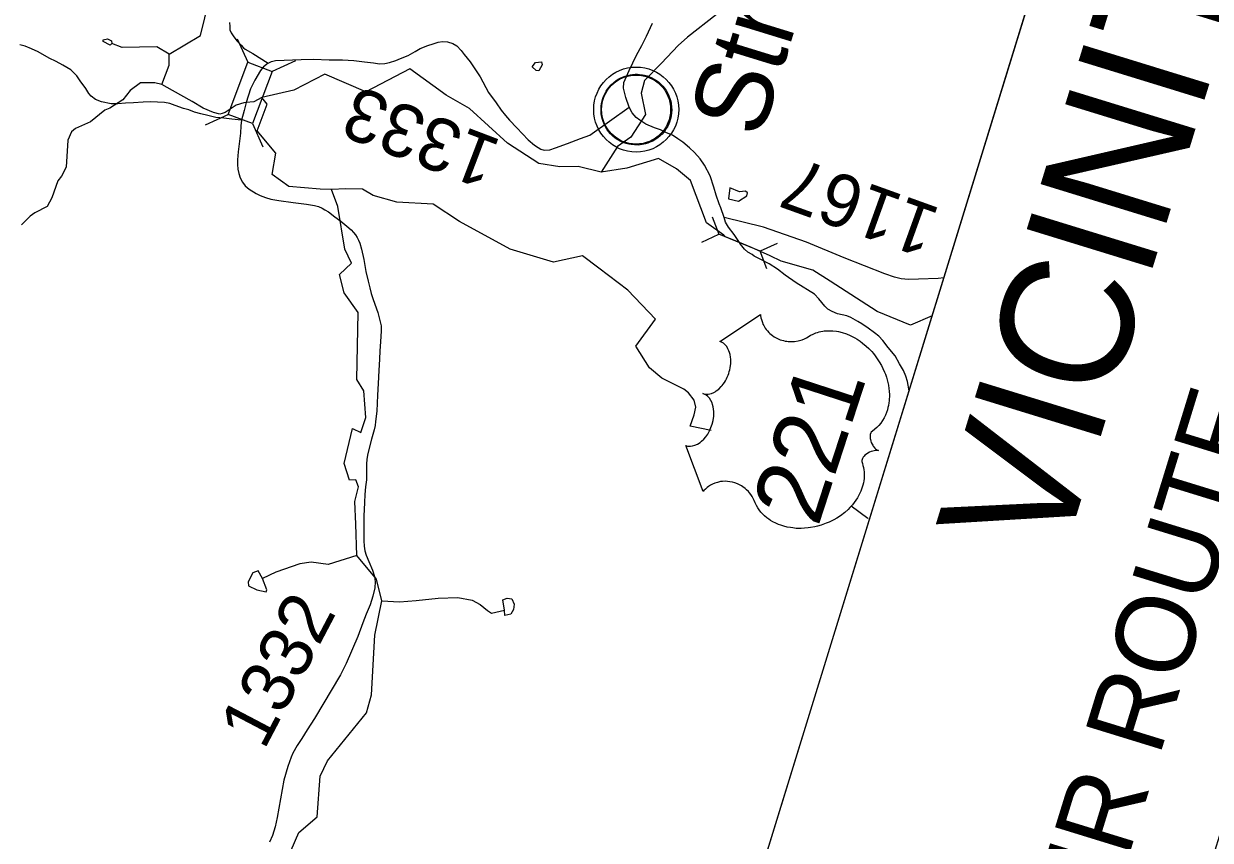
# Model space of a CAD drawing. Extents: x 1347947 to 1350662, y 1027710 to 1030532.
# Drawn here: x 1348252.2 to 1348353.5, y 1028802.3 to 1028872.1 of the extents above; entities that cross this region are included whole.
import ezdxf

# ---------------------------------------------------------------- set-up
doc = ezdxf.new("R2010")
doc.units = 0
for name, color, linetype in [('Default', 7, 'Continuous'), ('Prop Leader Line Light', 7, 'Continuous'), ('Prop WCC CELL', 7, 'Continuous')]:
    doc.layers.add(name, color=color, linetype=linetype)

msp = doc.modelspace()

# ---------------------------------------------------------------- linework, layer by layer
at = {"layer": 'Default'}
for p, q in [((1348270.41, 1028870.75), (1348271.31, 1028868.76)), ((1348275.38, 1028868.88), (1348273.4, 1028867.98)), ((1348269.67, 1028864.29), (1348267.68, 1028863.39)), ((1348271.71, 1028863.52), (1348272.6, 1028861.54)), ((1348310.96, 1028855.55), (1348311.54, 1028854.06)), ((1348310.08, 1028853.4), (1348311.54, 1028854.06)), ((1348315.07, 1028852.61), (1348311.54, 1028854.06)), ((1348316.53, 1028853.27), (1348315.07, 1028852.61)), ((1348315.65, 1028851.12), (1348315.07, 1028852.61))]:
    msp.add_line(p, q, dxfattribs=at)
for points in [[(1348333.37, 1028883.64), (1348331.83, 1028883.24), (1348328.68, 1028882.36), (1348316.42, 1028876.72), (1348311.33, 1028872.83), (1348308.86, 1028870.92), (1348308.06, 1028870.18), (1348306.64, 1028868.69), (1348305.18, 1028867.21), (1348304.9, 1028866.11), (1348305.29, 1028864.31)], [(1348271.18, 1028865.33), (1348270.97, 1028865.29), (1348270.31, 1028865.1), (1348269.9, 1028864.8), (1348269.38, 1028864.48), (1348269.13, 1028864.38), (1348268.93, 1028864.32), (1348268.37, 1028864.48), (1348267.5, 1028864.83), (1348266.57, 1028865.4), (1348264.87, 1028866.34), (1348263.98, 1028866.86), (1348264.61, 1028868.51), (1348264.61, 1028869.45), (1348267.27, 1028871.06), (1348268.01, 1028874.08), (1348268.57, 1028875.2), (1348268.36, 1028876.03), (1348268.81, 1028878.77), (1348269.15, 1028880.07)], [(1348269.75, 1028872.17), (1348269.78, 1028871.81), (1348269.79, 1028871.54), (1348269.89, 1028871.29), (1348270.05, 1028871.01), (1348270.38, 1028870.59), (1348270.74, 1028870.23), (1348270.94, 1028869.99), (1348271.1, 1028869.87), (1348271.74, 1028869.52), (1348273.05, 1028868.69)], [(1348303.87, 1028864.92), (1348303.6, 1028865.75), (1348303.4, 1028866.56), (1348303.44, 1028867.02), (1348303.87, 1028868.06), (1348304.52, 1028869.36), (1348304.97, 1028870.2), (1348305.36, 1028870.99), (1348305.86, 1028872.09)], [(1348259.71, 1028870.37), (1348259.55, 1028870.22), (1348258.95, 1028870.54), (1348258.96, 1028870.69), (1348259.33, 1028870.77), (1348259.68, 1028870.58), (1348259.71, 1028870.37)], [(1348259.71, 1028870.37), (1348259.55, 1028870.22), (1348258.95, 1028870.54), (1348258.96, 1028870.69), (1348259.33, 1028870.77), (1348259.68, 1028870.58), (1348259.71, 1028870.37)], [(1348270.78, 1028863.82), (1348269.96, 1028863.91), (1348269.26, 1028863.97), (1348268.57, 1028864.04), (1348267.89, 1028864.2), (1348267.31, 1028864.34), (1348266.75, 1028864.51), (1348266.29, 1028864.71), (1348265.81, 1028864.81), (1348265.12, 1028865.07), (1348264.66, 1028865.23), (1348264.19, 1028865.32), (1348263.59, 1028865.35), (1348262.99, 1028865.37), (1348262.37, 1028865.36), (1348261.56, 1028865.3), (1348260.88, 1028865.27), (1348260.21, 1028865.2), (1348259.64, 1028865.21), (1348258.82, 1028865.39), (1348258.3, 1028865.57), (1348257.94, 1028865.85), (1348257.75, 1028866.1), (1348257.48, 1028866.51), (1348257.01, 1028867.16), (1348256.7, 1028867.59), (1348256.2, 1028868.11), (1348255.51, 1028868.52), (1348254.95, 1028868.84), (1348254.34, 1028869.12), (1348253.4, 1028869.64), (1348252.85, 1028869.92), (1348252.3, 1028870.13), (1348251.85, 1028870.25)], [(1348264.61, 1028869.45), (1348263.54, 1028870.07), (1348260.57, 1028870.03), (1348259.71, 1028870.37)], [(1348273.05, 1028868.69), (1348273.34, 1028868.82), (1348273.69, 1028868.9), (1348275.86, 1028868.99), (1348276.91, 1028869.03), (1348278.26, 1028868.96), (1348279.41, 1028868.98), (1348280.36, 1028868.91), (1348281.29, 1028868.8), (1348282.04, 1028868.71), (1348282.56, 1028868.63), (1348283.02, 1028868.66), (1348283.42, 1028868.75), (1348283.96, 1028868.92), (1348284.34, 1028869.07), (1348285.01, 1028869.35), (1348285.61, 1028869.67), (1348286.02, 1028869.93), (1348286.68, 1028870.18), (1348287.13, 1028870.34), (1348287.58, 1028870.49), (1348287.94, 1028870.53), (1348288.38, 1028870.5), (1348288.81, 1028870.37), (1348289.16, 1028870.17), (1348289.54, 1028869.77), (1348289.8, 1028869.42), (1348290.29, 1028868.79), (1348291.15, 1028867.52), (1348291.88, 1028866.19), (1348292.51, 1028865.3), (1348292.94, 1028864.68), (1348293.33, 1028864.22), (1348293.66, 1028863.81), (1348294.3, 1028863.15), (1348294.76, 1028862.64), (1348295.26, 1028862.14), (1348295.81, 1028861.67), (1348296.1, 1028861.47), (1348296.34, 1028861.33), (1348296.62, 1028861.26), (1348297.1, 1028861.27), (1348297.59, 1028861.44), (1348298.61, 1028861.83), (1348299.72, 1028862.26), (1348300.52, 1028862.52), (1348303.87, 1028864.92)], [(1348295.93, 1028868.05), (1348295.59, 1028868.37), (1348295.87, 1028868.75), (1348296.4, 1028868.81), (1348296.46, 1028868.54), (1348296.18, 1028868.02), (1348295.93, 1028868.05)], [(1348295.93, 1028868.05), (1348295.59, 1028868.37), (1348295.87, 1028868.75), (1348296.4, 1028868.81), (1348296.46, 1028868.54), (1348296.18, 1028868.02), (1348295.93, 1028868.05)], [(1348273.05, 1028868.69), (1348272.65, 1028868.37), (1348272.39, 1028868.07), (1348271.9, 1028867.22), (1348271.55, 1028866.49), (1348271.18, 1028865.33)], [(1348301.5, 1028859.36), (1348299.53, 1028859.84), (1348297.97, 1028859.82), (1348296.16, 1028860.12), (1348293.49, 1028861.85), (1348290.26, 1028864.81), (1348288.25, 1028865.96), (1348285.14, 1028868.19), (1348281.4, 1028866.23), (1348277.88, 1028867.75), (1348275.23, 1028866.37), (1348272.5, 1028865.75)], [(1348263.98, 1028866.86), (1348263.38, 1028867.01), (1348262.15, 1028866.99), (1348261.26, 1028866.36), (1348260.63, 1028865.56), (1348259.52, 1028864.83), (1348259.1, 1028864.67), (1348257.89, 1028863.67), (1348256.61, 1028863.09), (1348256.26, 1028862.81), (1348255.95, 1028862.1), (1348255.8, 1028859.81), (1348255.39, 1028859.04), (1348255.09, 1028858.63), (1348254.58, 1028857.18), (1348254.19, 1028856.43), (1348253.13, 1028855.89), (1348252.73, 1028855.62), (1348251.99, 1028854.86)], [(1348272.5, 1028865.75), (1348271.84, 1028865.39), (1348271.18, 1028865.33)], [(1348278.45, 1028857.9), (1348277.5, 1028857.93), (1348274.83, 1028858.14), (1348273.38, 1028859.18), (1348273.72, 1028860.99), (1348272.1, 1028862.9), (1348272.97, 1028865.19), (1348272.5, 1028865.75)], [(1348271.18, 1028865.33), (1348270.99, 1028864.64), (1348270.78, 1028863.82)], [(1348312, 1028855.49), (1348311.7, 1028856.31), (1348311.56, 1028856.66), (1348311.31, 1028857.41), (1348311.1, 1028858.09), (1348310.8, 1028859.05), (1348310.31, 1028859.98), (1348309.94, 1028860.51), (1348309.47, 1028861.05), (1348309.02, 1028861.46), (1348308.47, 1028861.92), (1348308.04, 1028862.22), (1348307.57, 1028862.52), (1348307.08, 1028862.73), (1348306.55, 1028862.98), (1348306.04, 1028863.16), (1348305.31, 1028863.47), (1348304.8, 1028863.8), (1348304.49, 1028864.03), (1348304.15, 1028864.43), (1348303.87, 1028864.92)], [(1348270.78, 1028863.82), (1348270.73, 1028863.33), (1348270.68, 1028862.71), (1348270.48, 1028861.1), (1348270.43, 1028860.41), (1348270.43, 1028860.03), (1348270.46, 1028859.63), (1348270.55, 1028859.26), (1348270.67, 1028858.88), (1348270.86, 1028858.51), (1348271.09, 1028858.19), (1348271.42, 1028857.92), (1348272.03, 1028857.55), (1348272.38, 1028857.38), (1348272.83, 1028857.2), (1348273.28, 1028857.06), (1348273.95, 1028856.94), (1348275.2, 1028856.77), (1348276.33, 1028856.63), (1348277, 1028856.51), (1348277.36, 1028856.43), (1348277.66, 1028856.3), (1348277.9, 1028856.16), (1348278.2, 1028855.98), (1348278.75, 1028855.56), (1348279.27, 1028855.17), (1348279.78, 1028854.76), (1348280.15, 1028854.43), (1348280.34, 1028854.22), (1348280.51, 1028854.02), (1348280.66, 1028853.79), (1348280.76, 1028853.56), (1348280.87, 1028853.29), (1348281.01, 1028852.79), (1348281.22, 1028851.9), (1348281.4, 1028850.89), (1348281.59, 1028850.04), (1348281.73, 1028849.47), (1348281.86, 1028848.99), (1348282.02, 1028848.49), (1348282.41, 1028847.37), (1348282.59, 1028846.69), (1348282.69, 1028846.23), (1348282.69, 1028845.81), (1348282.64, 1028844.87), (1348282.6, 1028844.11), (1348282.55, 1028843.39), (1348282.51, 1028842.41), (1348282.45, 1028841.31), (1348282.4, 1028840.3), (1348282.33, 1028838.95), (1348282.22, 1028838.07), (1348282.18, 1028837.71), (1348282.1, 1028837.36), (1348281.87, 1028836.54), (1348281.64, 1028835.68), (1348281.53, 1028835.18), (1348281.49, 1028834.82), (1348281.46, 1028834.45), (1348281.45, 1028833.56), (1348281.45, 1028833.08), (1348281.37, 1028832.47), (1348281.31, 1028831.82), (1348281.27, 1028831.13), (1348281.23, 1028829.98), (1348281.21, 1028828.59), (1348281.21, 1028827.85), (1348281.24, 1028827.4), (1348281.32, 1028827), (1348281.43, 1028826.64), (1348281.64, 1028826.09), (1348281.97, 1028825.36), (1348282.14, 1028824.81), (1348282.19, 1028824.35), (1348282.16, 1028823.84), (1348282, 1028823.12), (1348281.75, 1028822.39), (1348281.41, 1028821.6), (1348281.14, 1028820.86), (1348280.72, 1028819.69), (1348279.71, 1028817.37), (1348279.24, 1028816.4), (1348277, 1028812.67), (1348276.39, 1028811.71), (1348275.93, 1028810.98), (1348275.54, 1028810.38), (1348275.17, 1028809.72), (1348275.01, 1028809.37), (1348274.72, 1028808.58), (1348274.4, 1028807.42), (1348274.11, 1028805.82), (1348273.81, 1028804.21), (1348273.64, 1028803.42), (1348273.43, 1028802.68), (1348273.17, 1028802.12)], [(1348305.29, 1028864.31), (1348304.01, 1028862.37)], [(1348304.01, 1028862.37), (1348302.89, 1028861.55)], [(1348302.89, 1028861.55), (1348301.5, 1028859.36)], [(1348313.29, 1028853.37), (1348312.11, 1028853.85), (1348311.96, 1028853.99), (1348310.5, 1028855.04), (1348309.11, 1028858.67), (1348307.92, 1028859.64), (1348306.39, 1028860.53), (1348303.69, 1028859.71), (1348301.5, 1028859.36)], [(1348274.35, 1028799.93), (1348275.67, 1028802.95), (1348277.23, 1028804.28), (1348277.5, 1028807.75), (1348278.13, 1028809.06), (1348281.46, 1028813.16), (1348281.89, 1028814.7), (1348282.16, 1028819.8), (1348282.75, 1028822.73), (1348282.29, 1028824.59), (1348280.62, 1028826.62), (1348280.55, 1028829.28), (1348280.46, 1028831.23), (1348280.76, 1028832.49), (1348280.55, 1028833.07), (1348279.99, 1028833.05), (1348279.55, 1028834.48), (1348280.25, 1028837.47), (1348280.96, 1028837.12), (1348281.38, 1028838.4), (1348281.21, 1028840.67), (1348280.62, 1028841.65), (1348280.74, 1028847.37), (1348279.54, 1028849.07), (1348279.13, 1028850.61), (1348280.18, 1028851.58), (1348279.61, 1028852.78), (1348278.99, 1028856.44), (1348278.45, 1028857.9)], [(1348310.89, 1028837.28), (1348309.08, 1028837.66), (1348309.44, 1028838.64), (1348309.57, 1028839.29), (1348309.43, 1028839.87), (1348308.95, 1028840.51), (1348308.54, 1028840.82), (1348306.66, 1028841.75), (1348305.61, 1028842.66), (1348304.45, 1028844.5), (1348306.14, 1028846.81), (1348303.78, 1028849.28), (1348301.3, 1028851.17), (1348299.9, 1028852.22), (1348297.41, 1028851.69), (1348293.71, 1028852.8), (1348289.4, 1028855.15), (1348287.14, 1028856.62), (1348284.05, 1028856.81), (1348282.03, 1028857.38), (1348281.11, 1028857.93), (1348279.69, 1028857.94), (1348278.45, 1028857.9)], [(1348312.36, 1028857.1), (1348313.23, 1028856.9), (1348313.94, 1028857.36), (1348313.98, 1028857.59), (1348313.83, 1028857.74), (1348313.3, 1028857.69), (1348312.49, 1028858.03), (1348312.36, 1028857.1)], [(1348330.75, 1028850.33), (1348330.26, 1028850.29), (1348328.58, 1028850.23), (1348327.77, 1028850.21), (1348327.41, 1028850.23), (1348327.11, 1028850.26), (1348326.53, 1028850.4), (1348325.71, 1028850.67), (1348322.23, 1028852.04), (1348319.04, 1028853.4), (1348315.36, 1028854.67), (1348312, 1028855.49)], [(1348327.78, 1028840.69), (1348327.64, 1028841.48), (1348327.51, 1028841.94), (1348327.31, 1028842.41), (1348326.97, 1028843), (1348326.59, 1028843.66), (1348326, 1028844.38), (1348325.54, 1028844.99), (1348325.21, 1028845.34), (1348324.82, 1028845.64), (1348324.29, 1028846.05), (1348323.75, 1028846.42), (1348323.4, 1028846.62), (1348322.82, 1028846.95), (1348322.46, 1028847.1), (1348321.68, 1028847.27), (1348321.22, 1028847.46), (1348320.85, 1028847.66), (1348320.59, 1028847.91), (1348320.08, 1028848.54), (1348319.72, 1028848.93), (1348318.13, 1028849.91), (1348317.2, 1028850.57), (1348316.56, 1028851.09), (1348315.84, 1028851.53), (1348315.07, 1028851.92), (1348314.55, 1028852.2), (1348314.39, 1028852.32), (1348314.01, 1028852.53), (1348313.72, 1028852.8), (1348313.38, 1028853.22), (1348313.29, 1028853.37), (1348312.86, 1028854.03), (1348312.37, 1028854.66), (1348312.11, 1028855.11), (1348312, 1028855.49)], [(1348316.85, 1028851.75), (1348315.91, 1028852.22), (1348314.34, 1028852.94), (1348313.29, 1028853.37)], [(1348319.58, 1028850.99), (1348316.85, 1028851.75)], [(1348329.76, 1028847.09), (1348327.9, 1028846.28), (1348325.06, 1028847.45), (1348321.05, 1028850.06), (1348319.58, 1028850.99)], [(1348324.27, 1028829.76), (1348322.84, 1028830.82)], [(1348324.41, 1028829.72), (1348324.36, 1028829.73)], [(1348280.62, 1028826.62), (1348278.19, 1028825.83), (1348276.73, 1028826.03), (1348275.77, 1028825.9), (1348273.72, 1028825.19), (1348272.57, 1028824.63)], [(1348272.57, 1028824.63), (1348272.2, 1028825.31), (1348271.73, 1028825.13), (1348271.35, 1028824.35), (1348271.38, 1028824.03), (1348272.08, 1028823.68), (1348272.89, 1028823.5), (1348272.95, 1028823.68), (1348272.57, 1028824.63)], [(1348272.57, 1028824.63), (1348272.2, 1028825.31), (1348271.73, 1028825.13), (1348271.35, 1028824.35), (1348271.38, 1028824.03), (1348272.08, 1028823.68), (1348272.89, 1028823.5), (1348272.95, 1028823.68), (1348272.57, 1028824.63)], [(1348282.75, 1028822.73), (1348284.27, 1028822.64), (1348285.7, 1028822.75), (1348287.56, 1028822.95), (1348289.26, 1028823.03), (1348290.46, 1028822.78), (1348291.15, 1028822.43), (1348291.78, 1028821.9), (1348292.12, 1028821.69), (1348293.23, 1028821.95)], [(1348293.23, 1028821.95), (1348293.1, 1028822.81), (1348293.46, 1028822.95), (1348293.85, 1028822.91), (1348294.05, 1028822.44), (1348293.99, 1028821.99), (1348293.78, 1028821.61), (1348293.27, 1028821.49), (1348293.23, 1028821.95)], [(1348293.23, 1028821.95), (1348293.1, 1028822.81), (1348293.46, 1028822.95), (1348293.85, 1028822.91), (1348294.05, 1028822.44), (1348293.99, 1028821.99), (1348293.78, 1028821.61), (1348293.27, 1028821.49), (1348293.23, 1028821.95)]]:
    msp.add_lwpolyline(points, dxfattribs=at)
for points in [[(1348273.4, 1028867.98), (1348271.72, 1028863.52), (1348269.63, 1028864.3), (1348271.31, 1028868.76)], [(1348303.1, 1028862.03), (1348302.91, 1028862.14), (1348302.69, 1028862.28), (1348302.46, 1028862.47), (1348302.29, 1028862.65), (1348302.12, 1028862.84), (1348301.97, 1028863.04), (1348301.86, 1028863.23), (1348301.75, 1028863.46), (1348301.65, 1028863.71), (1348301.58, 1028863.96), (1348301.53, 1028864.17), (1348301.5, 1028864.38), (1348301.48, 1028864.61), (1348301.48, 1028864.84), (1348301.49, 1028865.01), (1348301.52, 1028865.2), (1348301.54, 1028865.35), (1348301.61, 1028865.59), (1348301.67, 1028865.75), (1348301.74, 1028865.96), (1348301.83, 1028866.13), (1348301.92, 1028866.29), (1348302.04, 1028866.46), (1348302.17, 1028866.63), (1348302.35, 1028866.84), (1348302.56, 1028867.02), (1348302.75, 1028867.17), (1348302.95, 1028867.31), (1348303.11, 1028867.39), (1348303.32, 1028867.49), (1348303.54, 1028867.57), (1348303.74, 1028867.63), (1348303.96, 1028867.69), (1348304.18, 1028867.72), (1348304.39, 1028867.73), (1348304.59, 1028867.73), (1348304.77, 1028867.72), (1348305.01, 1028867.69), (1348305.19, 1028867.65), (1348305.41, 1028867.59), (1348305.62, 1028867.52), (1348305.82, 1028867.43), (1348306.01, 1028867.33), (1348306.21, 1028867.2), (1348306.41, 1028867.06), (1348306.56, 1028866.91), (1348306.75, 1028866.73), (1348306.9, 1028866.54), (1348307.03, 1028866.36), (1348307.16, 1028866.15), (1348307.27, 1028865.9), (1348307.36, 1028865.66), (1348307.43, 1028865.44), (1348307.47, 1028865.25), (1348307.51, 1028864.96), (1348307.52, 1028864.67), (1348307.51, 1028864.43), (1348307.47, 1028864.18), (1348307.44, 1028864.01), (1348307.39, 1028863.84), (1348307.33, 1028863.64), (1348307.26, 1028863.49), (1348307.17, 1028863.29), (1348307.05, 1028863.09), (1348306.95, 1028862.94), (1348306.82, 1028862.77), (1348306.69, 1028862.62), (1348306.56, 1028862.51), (1348306.33, 1028862.31), (1348306.11, 1028862.15), (1348305.89, 1028862.03), (1348305.66, 1028861.92), (1348305.47, 1028861.85), (1348305.28, 1028861.79), (1348304.98, 1028861.73), (1348304.83, 1028861.71), (1348304.66, 1028861.69), (1348304.33, 1028861.7), (1348304.05, 1028861.72), (1348303.85, 1028861.76), (1348303.62, 1028861.82), (1348303.45, 1028861.88), (1348303.22, 1028861.97)], [(1348308.73, 1028836), (1348308.86, 1028835.96), (1348309.03, 1028835.95), (1348309.11, 1028835.94), (1348309.29, 1028835.97), (1348309.5, 1028836.03), (1348309.73, 1028836.13), (1348309.94, 1028836.27), (1348310.07, 1028836.37), (1348310.25, 1028836.54), (1348310.43, 1028836.75), (1348310.59, 1028836.99), (1348310.74, 1028837.25), (1348310.87, 1028837.54), (1348310.97, 1028837.83), (1348311.05, 1028838.16), (1348311.1, 1028838.53), (1348311.11, 1028838.71), (1348311.1, 1028838.91), (1348311.09, 1028839.11), (1348311.05, 1028839.32), (1348311, 1028839.5), (1348310.96, 1028839.65), (1348310.85, 1028839.86), (1348310.73, 1028840.05), (1348310.66, 1028840.13), (1348310.59, 1028840.21), (1348310.42, 1028840.34), (1348310.34, 1028840.38), (1348310.17, 1028840.45), (1348310.32, 1028840.41), (1348310.42, 1028840.4), (1348310.51, 1028840.4), (1348310.62, 1028840.4), (1348310.77, 1028840.42), (1348310.91, 1028840.46), (1348311.12, 1028840.55), (1348311.22, 1028840.61), (1348311.31, 1028840.67), (1348311.53, 1028840.83), (1348311.73, 1028841.04), (1348311.83, 1028841.14), (1348311.91, 1028841.25), (1348312.01, 1028841.39), (1348312.1, 1028841.54), (1348312.18, 1028841.7), (1348312.26, 1028841.85), (1348312.33, 1028842.02), (1348312.38, 1028842.16), (1348312.43, 1028842.33), (1348312.47, 1028842.48), (1348312.51, 1028842.65), (1348312.53, 1028842.84), (1348312.55, 1028842.99), (1348312.56, 1028843.19), (1348312.55, 1028843.38), (1348312.54, 1028843.55), (1348312.5, 1028843.78), (1348312.45, 1028843.96), (1348312.4, 1028844.11), (1348312.32, 1028844.28), (1348312.21, 1028844.46), (1348312.13, 1028844.57), (1348312.03, 1028844.66), (1348311.93, 1028844.75), (1348311.82, 1028844.82), (1348311.71, 1028844.87), (1348311.62, 1028844.9), (1348315.11, 1028847.21), (1348315.11, 1028847.12), (1348315.14, 1028846.93), (1348315.18, 1028846.77), (1348315.26, 1028846.51), (1348315.31, 1028846.39), (1348315.37, 1028846.27), (1348315.43, 1028846.15), (1348315.49, 1028846.05), (1348315.59, 1028845.92), (1348315.69, 1028845.8), (1348315.8, 1028845.67), (1348315.9, 1028845.58), (1348316.12, 1028845.4), (1348316.26, 1028845.3), (1348316.39, 1028845.23), (1348316.65, 1028845.1), (1348316.78, 1028845.05), (1348316.91, 1028845.01), (1348317.05, 1028844.97), (1348317.19, 1028844.94), (1348317.34, 1028844.92), (1348317.46, 1028844.9), (1348317.63, 1028844.89), (1348317.82, 1028844.89), (1348318.01, 1028844.9), (1348318.32, 1028844.96), (1348318.66, 1028845.05), (1348318.85, 1028845.13), (1348319.03, 1028845.22), (1348319.25, 1028845.36), (1348319.38, 1028845.43), (1348319.54, 1028845.51), (1348319.83, 1028845.63), (1348319.96, 1028845.68), (1348320.1, 1028845.72), (1348320.25, 1028845.75), (1348320.41, 1028845.78), (1348320.54, 1028845.8), (1348320.85, 1028845.82), (1348321.13, 1028845.82), (1348321.28, 1028845.81), (1348321.6, 1028845.77), (1348321.76, 1028845.74), (1348322.07, 1028845.67), (1348322.43, 1028845.56), (1348322.76, 1028845.42), (1348323.14, 1028845.22), (1348323.36, 1028845.09), (1348323.61, 1028844.92), (1348323.82, 1028844.76), (1348324.13, 1028844.5), (1348324.35, 1028844.29), (1348324.6, 1028844.03), (1348324.74, 1028843.86), (1348324.9, 1028843.67), (1348325.07, 1028843.43), (1348325.24, 1028843.16), (1348325.42, 1028842.85), (1348325.55, 1028842.6), (1348325.68, 1028842.29), (1348325.76, 1028842.1), (1348325.85, 1028841.84), (1348325.94, 1028841.5), (1348326.02, 1028841.16), (1348326.06, 1028840.88), (1348326.08, 1028840.64), (1348326.1, 1028840.33), (1348326.08, 1028839.82), (1348326.06, 1028839.65), (1348326.02, 1028839.44), (1348325.98, 1028839.25), (1348325.93, 1028839.06), (1348325.85, 1028838.82), (1348325.76, 1028838.59), (1348325.65, 1028838.37), (1348325.52, 1028838.15), (1348325.37, 1028837.92), (1348325.21, 1028837.73), (1348325.02, 1028837.54), (1348324.65, 1028837.23), (1348324.56, 1028837.14), (1348324.52, 1028837.08), (1348324.46, 1028836.94), (1348324.45, 1028836.79), (1348324.46, 1028836.62), (1348324.48, 1028836.52), (1348324.51, 1028836.38), (1348324.56, 1028836.27), (1348324.62, 1028836.13), (1348324.68, 1028836.03), (1348324.73, 1028835.95), (1348324.87, 1028835.79), (1348324.93, 1028835.73), (1348325.03, 1028835.65), (1348325.17, 1028835.57), (1348324.96, 1028835.58), (1348324.81, 1028835.56), (1348324.68, 1028835.53), (1348324.56, 1028835.5), (1348324.4, 1028835.43), (1348324.27, 1028835.36), (1348324.14, 1028835.28), (1348324.02, 1028835.18), (1348323.94, 1028835.09), (1348323.87, 1028835.01), (1348323.81, 1028834.91), (1348323.77, 1028834.82), (1348323.75, 1028834.74), (1348323.74, 1028834.63), (1348323.8, 1028834.46), (1348323.84, 1028834.3), (1348323.89, 1028834.12), (1348323.92, 1028833.92), (1348323.94, 1028833.77), (1348323.95, 1028833.6), (1348323.95, 1028833.41), (1348323.94, 1028833.2), (1348323.91, 1028832.99), (1348323.89, 1028832.81), (1348323.84, 1028832.62), (1348323.79, 1028832.45), (1348323.73, 1028832.28), (1348323.67, 1028832.12), (1348323.59, 1028831.93), (1348323.48, 1028831.71), (1348323.37, 1028831.53), (1348323.25, 1028831.34), (1348323.11, 1028831.15), (1348322.95, 1028830.95), (1348322.74, 1028830.71), (1348322.57, 1028830.55), (1348322.29, 1028830.29), (1348321.92, 1028830.01), (1348321.61, 1028829.81), (1348321.36, 1028829.67), (1348320.97, 1028829.47), (1348320.71, 1028829.36), (1348320.27, 1028829.2), (1348319.96, 1028829.11), (1348319.74, 1028829.06), (1348319.38, 1028828.99), (1348319.16, 1028828.96), (1348318.85, 1028828.94), (1348318.57, 1028828.92), (1348318.3, 1028828.93), (1348318.13, 1028828.93), (1348317.85, 1028828.96), (1348317.65, 1028828.99), (1348317.38, 1028829.04), (1348317.1, 1028829.11), (1348316.84, 1028829.19), (1348316.64, 1028829.26), (1348316.4, 1028829.36), (1348316.15, 1028829.49), (1348315.95, 1028829.61), (1348315.8, 1028829.71), (1348315.63, 1028829.84), (1348315.44, 1028829.99), (1348315.27, 1028830.16), (1348315.13, 1028830.32), (1348314.99, 1028830.5), (1348314.87, 1028830.67), (1348314.75, 1028830.89), (1348314.65, 1028831.11), (1348314.57, 1028831.3), (1348314.45, 1028831.53), (1348314.38, 1028831.66), (1348314.27, 1028831.82), (1348314.16, 1028831.96), (1348314.06, 1028832.07), (1348313.91, 1028832.23), (1348313.79, 1028832.33), (1348313.6, 1028832.47), (1348313.47, 1028832.55), (1348313.29, 1028832.65), (1348313.12, 1028832.73), (1348312.9, 1028832.81), (1348312.72, 1028832.87), (1348312.49, 1028832.91), (1348312.27, 1028832.94), (1348312.08, 1028832.95), (1348311.85, 1028832.94), (1348311.67, 1028832.92), (1348311.43, 1028832.86), (1348311.2, 1028832.79), (1348311, 1028832.71), (1348310.82, 1028832.61), (1348310.67, 1028832.52), (1348310.54, 1028832.42), (1348310.39, 1028832.29), (1348310.27, 1028832.16), (1348310.2, 1028832.08)]]:
    msp.add_lwpolyline(points, close=True, dxfattribs=at)
for centre, radius in [((1348304.48, 1028864.72), 3.63), ((1348304.47, 1028864.72), 2.95)]:
    msp.add_circle(centre, radius, dxfattribs=at)
at = {"layer": 'Prop WCC CELL'}
msp.add_line((1348285.23, 1028702.5), (1348393.41, 1029053.78), dxfattribs=at)
msp.add_lwpolyline([(1348285.23, 1028702.5), (1348393.41, 1029053.78), (1348428.36, 1029043.07), (1348320.15, 1028691.84)], close=True, dxfattribs=at)

# ---------------------------------------------------------------- texts
at = {"layer": 'Default'}
msp.add_text('221', height=6.002, rotation=71.9667, dxfattribs=at).set_placement((1348320, 1028828.97))
at = {"layer": 'Prop Leader Line Light'}
for s, height, rotation, p in [('VICINITY MAP', 11.25, 72.8834, (1348340.8, 1028825.9)), ('Stratford', 6.5, 72.8834, (1348315.12, 1028862.11)), ('1333', 4.5, 159.1497, (1348293.12, 1028862.03)), ('1167', 4.5, 160.2007, (1348330.62, 1028856.2)), ('DETOUR ROUTE', 6.75, 72.8834, (1348337.19, 1028770.5)), ('1332', 4.5, 62.2786, (1348272.69, 1028809.9))]:
    msp.add_text(s, height=height, rotation=rotation, dxfattribs=at).set_placement(p)

doc.saveas('drawing.dxf')
